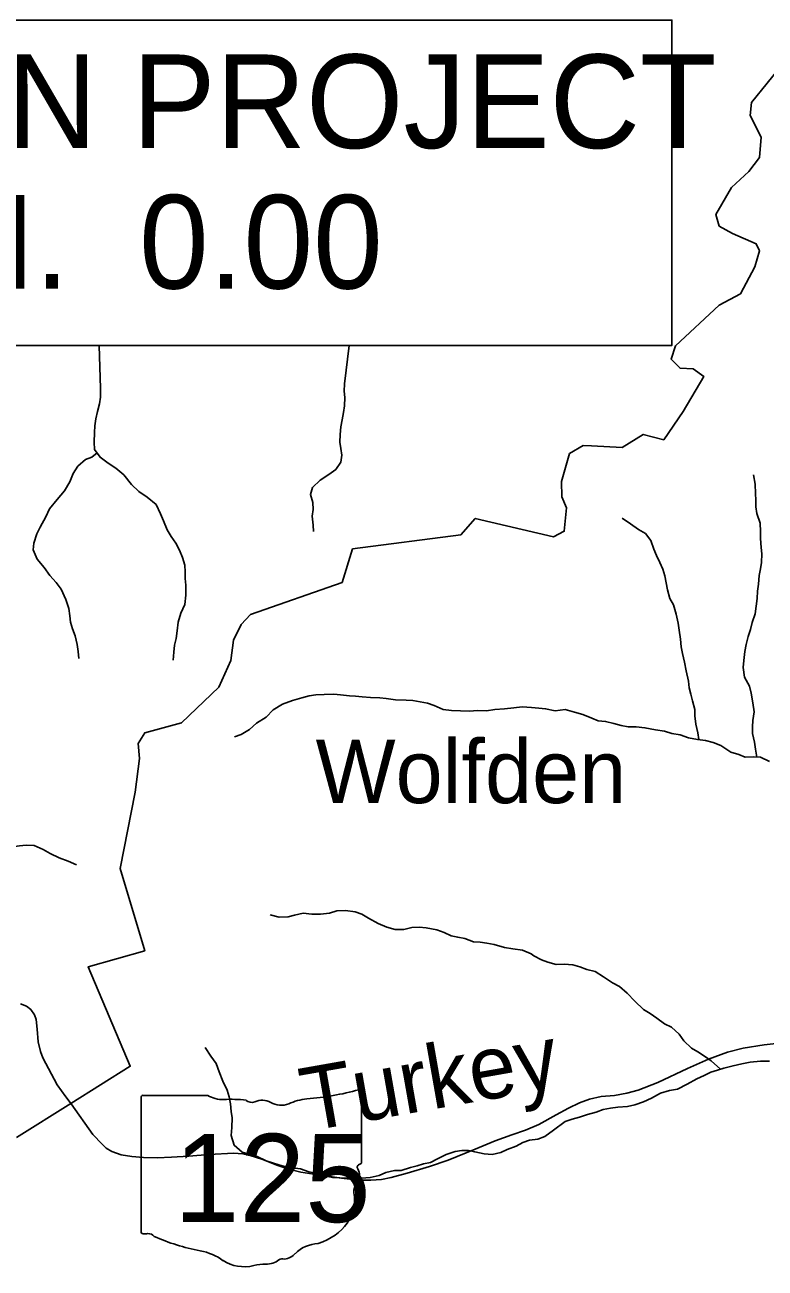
# Model space of a CAD drawing. Extents: x 0 to 34, y 0 to 22.
# Drawn here: x 3.475 to 4.582, y 17.294 to 19.152 of the extents above; entities that cross this region are included whole.
import ezdxf

# ---------------------------------------------------------------- set-up
doc = ezdxf.new("R2010")
doc.units = 0
for name, color, linetype in [('Default', 7, 'Continuous'), ('GM_X_Minor_River', 7, 'Continuous'), ('GM_X_Minor_River_Text', 7, 'Continuous'), ('GM_X_State_Location', 7, 'Continuous'), ('GM_X_State_Route', 7, 'Continuous'), ('GM_X_State_Shield', 7, 'Continuous'), ('SH_Text', 7, 'Continuous')]:
    doc.layers.add(name, color=color, linetype=linetype)

msp = doc.modelspace()

# ---------------------------------------------------------------- linework, layer by layer
at = {"layer": 'Default'}
for points in [[(4.632, 19.1229), (4.5616, 19.0361), (4.5599, 19.0167), (4.5761, 18.9842), (4.5739, 18.9539), (4.5577, 18.9328), (4.532, 18.9089), (4.5084, 18.8685), (4.5132, 18.8514), (4.5335, 18.8405), (4.5689, 18.8249), (4.5737, 18.8146), (4.5666, 18.7904), (4.5453, 18.75), (4.5136, 18.7333), (4.4481, 18.6723), (4.4414, 18.6522), (4.4549, 18.6388), (4.4746, 18.6381), (4.4907, 18.6265), (4.4594, 18.5742), (4.4305, 18.532), (4.3999, 18.54), (4.3683, 18.5203), (4.3226, 18.5229), (4.31, 18.5236), (4.2894, 18.5114), (4.2775, 18.4698), (4.278, 18.4466), (4.2854, 18.4302), (4.2819, 18.3953), (4.2655, 18.3871), (4.1488, 18.4144), (4.1273, 18.39), (3.9654, 18.3689), (3.9496, 18.3186), (3.8127, 18.271), (3.7985, 18.2556), (3.7872, 18.2322), (3.7831, 18.2022), (3.7652, 18.1622), (3.7096, 18.1086), (3.6545, 18.0938), (3.6445, 18.0779), (3.6465, 18.0555), (3.6402, 18.0051), (3.6176, 17.8911), (3.6545, 17.7681), (3.5702, 17.7442), (3.6328, 17.5954), (3.5442, 17.5398), (3.4629, 17.4891)], [(3.4629, 17.4891), (3.5442, 17.5398), (3.6328, 17.5954), (3.5702, 17.7442), (3.6545, 17.7681), (3.6176, 17.8911), (3.6402, 18.0051), (3.6465, 18.0555), (3.6445, 18.0779), (3.6545, 18.0938), (3.7096, 18.1086), (3.7652, 18.1622), (3.7831, 18.2022), (3.7872, 18.2322), (3.7985, 18.2556), (3.8127, 18.271), (3.9496, 18.3186), (3.9654, 18.3689), (4.1273, 18.39), (4.1488, 18.4144), (4.2655, 18.3871), (4.2819, 18.3953), (4.2854, 18.4302), (4.278, 18.4466), (4.2775, 18.4698), (4.2894, 18.5114), (4.31, 18.5236), (4.3226, 18.5229), (4.3683, 18.5203), (4.3999, 18.54), (4.4305, 18.532), (4.4594, 18.5742), (4.4907, 18.6265), (4.4746, 18.6381), (4.4549, 18.6388), (4.4414, 18.6522), (4.4481, 18.6723), (4.5136, 18.7333), (4.5453, 18.75), (4.5666, 18.7904), (4.5737, 18.8146), (4.5689, 18.8249), (4.5335, 18.8405), (4.5132, 18.8514), (4.5084, 18.8685), (4.532, 18.9089), (4.5577, 18.9328), (4.5739, 18.9539), (4.5761, 18.9842), (4.5599, 19.0167), (4.5616, 19.0361), (4.632, 19.1229)]]:
    msp.add_lwpolyline(points, dxfattribs=at)
at = {"layer": 'GM_X_Minor_River'}
for points in [[(3.5866, 18.673), (3.5885, 18.6087), (3.5884, 18.5958), (3.5868, 18.5859), (3.5841, 18.5742), (3.5814, 18.5632), (3.5802, 18.5526), (3.5797, 18.5427), (3.5792, 18.5283), (3.5796, 18.5176), (3.5878, 18.5058), (3.5999, 18.497), (3.6112, 18.4893), (3.6233, 18.4797), (3.6349, 18.4652), (3.6459, 18.4545), (3.658, 18.4461), (3.6715, 18.4354), (3.6783, 18.4213), (3.6827, 18.4106), (3.688, 18.3973), (3.694, 18.3874), (3.7011, 18.3774), (3.7067, 18.3671), (3.7112, 18.3561), (3.7145, 18.3443), (3.7148, 18.3344), (3.7148, 18.3246), (3.7162, 18.3147), (3.7161, 18.2999), (3.7145, 18.2858), (3.7087, 18.2726), (3.7045, 18.2593), (3.7033, 18.2464), (3.7017, 18.235), (3.6993, 18.2248), (3.6981, 18.2145), (3.6973, 18.2024)], [(3.9602, 18.673), (3.953, 18.6155), (3.9529, 18.6045), (3.9536, 18.595), (3.9531, 18.5828), (3.9519, 18.5726), (3.9499, 18.5616), (3.948, 18.5513), (3.9468, 18.54), (3.9463, 18.5282), (3.9478, 18.5187), (3.9492, 18.5088), (3.9476, 18.4986), (3.9404, 18.4876), (3.9297, 18.4801), (3.9167, 18.4718), (3.9053, 18.4605), (3.9022, 18.4502), (3.9059, 18.438), (3.9066, 18.4278), (3.905, 18.4179), (3.9064, 18.4042), (3.9071, 18.3947)], [(3.5833, 18.5123), (3.5757, 18.5059), (3.5662, 18.5025), (3.5544, 18.4923), (3.5478, 18.4814), (3.5424, 18.4689), (3.5348, 18.4556), (3.5237, 18.4428), (3.5122, 18.4288), (3.5068, 18.417), (3.498, 18.4015), (3.4934, 18.3913), (3.4888, 18.3773), (3.4879, 18.3674), (3.4939, 18.3537), (3.5041, 18.3411), (3.5127, 18.3293), (3.5221, 18.3186), (3.5296, 18.3086), (3.5364, 18.2934), (3.5412, 18.2797), (3.5426, 18.2687), (3.5437, 18.2592), (3.5467, 18.2493), (3.5508, 18.239), (3.5537, 18.2257), (3.5548, 18.2154), (3.5562, 18.2048)], [(4.5695, 18.0576), (4.5678, 18.0695), (4.5663, 18.0798), (4.5634, 18.0927), (4.5631, 18.1026), (4.5639, 18.1121), (4.5655, 18.1254), (4.5637, 18.1387), (4.5615, 18.1531), (4.5586, 18.1638), (4.5514, 18.1771), (4.5493, 18.1916), (4.5501, 18.2018), (4.5517, 18.2155), (4.554, 18.2257), (4.5568, 18.2379), (4.5603, 18.2485), (4.563, 18.2587), (4.5672, 18.2716), (4.5688, 18.2834), (4.5704, 18.2948), (4.5709, 18.3058), (4.5721, 18.316), (4.5733, 18.3289), (4.5753, 18.3392), (4.5769, 18.3487), (4.5773, 18.3612), (4.5762, 18.3707), (4.5752, 18.3844), (4.5753, 18.3946), (4.5746, 18.4072), (4.5698, 18.4216), (4.5683, 18.4315), (4.5684, 18.4418), (4.5677, 18.4517), (4.567, 18.4657), (4.5645, 18.4794)], [(4.4829, 18.0838), (4.4815, 18.094), (4.4785, 18.1066), (4.4771, 18.1191), (4.4768, 18.129), (4.4735, 18.1415), (4.4713, 18.1518), (4.4687, 18.1613), (4.4676, 18.1712), (4.4639, 18.1864), (4.4617, 18.1994), (4.4588, 18.2127), (4.4566, 18.2226), (4.4555, 18.234), (4.4537, 18.2473), (4.4523, 18.2579), (4.4493, 18.2712), (4.4452, 18.2853), (4.4396, 18.2948), (4.4363, 18.3078), (4.4322, 18.3287), (4.4293, 18.3386), (4.4248, 18.3485), (4.4196, 18.3588), (4.4158, 18.3683), (4.411, 18.3812), (4.4031, 18.3916), (4.3929, 18.3977), (4.3808, 18.4065), (4.3684, 18.4146)], [(4.5885, 18.0512), (4.5753, 18.0573), (4.5654, 18.0578), (4.5525, 18.0575), (4.5427, 18.0617), (4.531, 18.0652), (4.5159, 18.0748), (4.5045, 18.0794), (4.4932, 18.0822), (4.4811, 18.0841), (4.4674, 18.0865), (4.4553, 18.0911), (4.4428, 18.0931), (4.4315, 18.0962), (4.4182, 18.0986), (4.4023, 18.1014), (4.3894, 18.1026), (4.3773, 18.103), (4.3667, 18.1046), (4.3561, 18.1077), (4.3436, 18.1109), (4.3326, 18.1117), (4.3228, 18.1159), (4.3095, 18.1213), (4.297, 18.1248), (4.2834, 18.1287), (4.2682, 18.1269), (4.2538, 18.13), (4.244, 18.1309), (4.233, 18.1317), (4.219, 18.1325), (4.2064, 18.1311), (4.1924, 18.1297), (4.178, 18.1286), (4.1655, 18.1268), (4.1526, 18.1273), (4.1397, 18.1262), (4.1268, 18.1267), (4.1131, 18.1271), (4.1006, 18.1287), (4.0874, 18.1345), (4.0772, 18.1384), (4.0662, 18.1404), (4.0552, 18.1423), (4.0454, 18.1428), (4.0294, 18.1433), (4.0154, 18.1452), (4.006, 18.1464), (3.9919, 18.1465), (3.9798, 18.1477), (3.9699, 18.1486), (3.9605, 18.149), (3.9472, 18.1506), (3.9374, 18.1518), (3.9229, 18.1512), (3.9104, 18.1505), (3.9006, 18.149), (3.8895, 18.146), (3.8755, 18.142), (3.8607, 18.1367), (3.8466, 18.1285), (3.8359, 18.1175), (3.8218, 18.1081), (3.8111, 18.0987), (3.7985, 18.0912), (3.789, 18.0878)], [(3.443, 17.9225), (3.4539, 17.9232), (3.4675, 17.925), (3.4774, 17.9261), (3.4892, 17.9253), (3.5028, 17.9195), (3.513, 17.9133), (3.5266, 17.9072), (3.5402, 17.9018), (3.5527, 17.8967)], [(4.2324, 17.7633), (4.2192, 17.769), (4.2048, 17.771), (4.1923, 17.773), (4.1768, 17.7773), (4.1658, 17.7796), (4.1563, 17.7808), (4.1461, 17.7817), (4.1332, 17.7863), (4.1226, 17.7883), (4.1128, 17.7902), (4.1022, 17.7956), (4.0912, 17.7995), (4.0753, 17.8022), (4.0651, 17.8034), (4.0537, 17.8028), (4.0419, 17.7998), (4.0291, 17.7999), (4.0166, 17.8034), (4.0037, 17.8088), (3.9893, 17.8168), (3.9791, 17.8226), (3.9693, 17.8265), (3.9549, 17.8281), (3.9416, 17.8278), (3.9306, 17.8244), (3.9173, 17.823), (3.9044, 17.8227), (3.8916, 17.8243), (3.8787, 17.8213), (3.8688, 17.8188), (3.8555, 17.8181), (3.8423, 17.8216)], [(4.5152, 17.5912), (4.5017, 17.6036), (4.4915, 17.6105), (4.4816, 17.617), (4.4722, 17.6223), (4.4604, 17.6334), (4.4537, 17.6433), (4.4419, 17.6537), (4.4317, 17.659), (4.42, 17.6675), (4.4101, 17.6743), (4.4003, 17.6805), (4.3871, 17.6927), (4.3761, 17.7045), (4.3644, 17.7145), (4.3538, 17.7202), (4.3405, 17.729), (4.328, 17.7371), (4.3155, 17.7402), (4.3049, 17.7441), (4.2946, 17.7471), (4.2817, 17.748), (4.2699, 17.7477), (4.2574, 17.7512), (4.2476, 17.7546), (4.2363, 17.7607), (4.2324, 17.7633)], [(3.7536, 17.6105), (3.745, 17.6234)], [(4.5887, 17.6031), (4.5751, 17.6032), (4.5598, 17.6017), (4.5473, 17.5991), (4.5343, 17.5962), (4.5202, 17.5928), (4.5107, 17.5898), (4.5008, 17.5865), (4.4909, 17.5816), (4.4799, 17.5767), (4.4654, 17.5685), (4.4512, 17.5613), (4.4394, 17.5591), (4.4257, 17.5554), (4.4124, 17.5479), (4.4002, 17.5422), (4.3872, 17.5378), (4.3762, 17.5355), (4.3617, 17.5345), (4.3507, 17.5327), (4.3401, 17.5308), (4.3294, 17.5271), (4.3168, 17.5234), (4.3046, 17.5192), (4.2936, 17.5163), (4.2833, 17.5129), (4.2657, 17.5001), (4.2528, 17.4907), (4.2421, 17.4866), (4.2299, 17.4851), (4.22, 17.4814), (4.2097, 17.4761), (4.1964, 17.4709), (4.1868, 17.4668), (4.1739, 17.4638), (4.1621, 17.4646), (4.1481, 17.4674), (4.1386, 17.4697), (4.1287, 17.4694), (4.1188, 17.4679), (4.1051, 17.4634), (4.0925, 17.457), (4.0818, 17.4518), (4.0716, 17.4496), (4.062, 17.4466), (4.0518, 17.444), (4.038, 17.4399), (4.0282, 17.4395), (4.0152, 17.4366), (4.0049, 17.4321), (3.9916, 17.4291), (3.9787, 17.4284), (3.9665, 17.4278), (3.957, 17.4282), (3.9464, 17.4286), (3.9353, 17.4294), (3.9205, 17.4326), (3.9095, 17.4357), (3.9, 17.4376), (3.8875, 17.4419), (3.8754, 17.4438), (3.8598, 17.4466), (3.8469, 17.4505), (3.8359, 17.4543), (3.8226, 17.4605), (3.8101, 17.464), (3.8003, 17.467), (3.7882, 17.4774), (3.7837, 17.4922), (3.7849, 17.504), (3.7854, 17.5184), (3.7839, 17.5279), (3.7828, 17.5393), (3.781, 17.5496), (3.778, 17.5598), (3.7713, 17.5732), (3.766, 17.5872), (3.7612, 17.5998), (3.7536, 17.6105)]]:
    msp.add_lwpolyline(points, dxfattribs=at)
at = {"layer": 'GM_X_State_Route'}
msp.add_lwpolyline([(3.469, 17.689), (3.478, 17.6851), (3.4841, 17.6802), (3.4897, 17.6725), (3.492, 17.6652), (3.4939, 17.6507), (3.4953, 17.632), (3.4986, 17.6175), (3.5023, 17.608), (3.5238, 17.5679), (3.5367, 17.5498), (3.5445, 17.5393), (3.5771, 17.4936), (3.5911, 17.4789), (3.597, 17.4729), (3.6054, 17.4681), (3.6195, 17.4629), (3.6354, 17.4607), (3.6527, 17.459), (3.6732, 17.4587), (3.6944, 17.4598), (3.7204, 17.4612), (3.751, 17.4637), (3.7874, 17.4657), (3.8011, 17.4645), (3.8078, 17.4633), (3.8122, 17.4622), (3.8294, 17.4564), (3.8523, 17.4477), (3.8684, 17.4422), (3.8881, 17.4372), (3.9075, 17.4344), (3.9488, 17.4282), (3.965, 17.4262), (3.9803, 17.4254), (3.9927, 17.4252), (4.0088, 17.4264), (4.0231, 17.4291), (4.0469, 17.4356), (4.0802, 17.4458), (4.1081, 17.4549), (4.1487, 17.4715), (4.1785, 17.4841), (4.2034, 17.493), (4.224, 17.4999), (4.2439, 17.5084), (4.2699, 17.5231), (4.2883, 17.5328), (4.3044, 17.5408), (4.3197, 17.5463), (4.3369, 17.5501), (4.357, 17.5519), (4.3753, 17.5551), (4.3925, 17.5596), (4.4216, 17.5714), (4.4659, 17.5921), (4.4975, 17.6063), (4.5261, 17.6166), (4.5495, 17.6224), (4.5809, 17.6275), (4.6029, 17.6301)], dxfattribs=at)
at = {"layer": 'GM_X_State_Shield'}
for p, q in [((3.6491, 17.5486), (3.6491, 17.3484)), ((3.7489, 17.552), (3.6524, 17.552)), ((3.9787, 17.4523), (3.9787, 17.557)), ((3.9787, 17.4523), (3.9787, 17.4523))]:
    msp.add_line(p, q, dxfattribs=at)
for centre, major_axis, start_param, end_param in [((3.6529, 17.549), (0.00382, 0), 1.712693, 3.28349), ((3.7719, 17.5752), (0.037, 0), 4.042523, 4.731795), ((3.7842, 17.4397), (0.133, 0), 1.404758, 1.657858), ((3.8143, 17.55), (0.0107, 0), 3.836095, 5.185415), ((3.83, 17.5269), (0.0222, 0), 0.950623, 2.079405), ((3.9059, 17.4909), (0.0703, 0), 1.699011, 2.107814), ((3.8613, 17.8248), (0.3495, 0), 4.814394, 5.042369), ((3.9751, 17.5574), (0.00367, 0), 6.141152, 7.989035), ((3.8587, 17.5586), (0.0267, 0), 4.081561, 5.145723), ((3.9748, 17.4519), (0.00393, 0), 5.05454, 6.418171), ((3.9779, 17.4446), (0.00568, 0), 1.883978, 3.671073), ((3.9417, 17.4314), (0.0341, 0), 5.934695, 6.695948), ((3.9919, 17.4085), (0.0248, 0), 2.387724, 3.262537), ((3.8809, 17.3952), (0.0874, 0), 5.101752, 6.440018), ((3.6529, 17.348), (0.00385, 0), 3.00124, 4.508301), ((3.6535, 17.3685), (0.0294, 0), 4.665946, 4.897461), ((3.6595, 17.3369), (0.0106, 0), 0.519207, 1.627899), ((3.7934, 17.5167), (0.2524, 0), 4.195997, 4.488961), ((3.9178, 17.2923), (0.0479, 0), 1.647645, 2.488434), ((3.7181, 17.2585), (0.079, 0), 0.823519, 1.323587), ((3.8035, 17.3359), (0.0501, 0), 4.026481, 4.996735), ((3.8361, 17.3209), (0.0267, 0), 4.691044, 5.507374), ((3.8603, 17.3015), (0.00752, 0), 1.147584, 2.315152), ((3.8571, 17.329), (0.0282, 0), 4.937069, 5.64225), ((3.8325, 17.2667), (0.0412, 0), 1.495662, 1.94098)]:
    msp.add_ellipse(centre, major_axis=major_axis, ratio=0.8, start_param=start_param, end_param=end_param, dxfattribs=at)
at = {"layer": 'SH_Text'}
msp.add_lwpolyline([(2.9469, 19.1594), (4.4427, 19.1594), (4.4427, 18.673), (2.9469, 18.673)], close=True, dxfattribs=at)

# ---------------------------------------------------------------- texts
at = {"layer": 'GM_X_Minor_River_Text'}
for s, rotation, p in [('Wolfden', 0.0002, (3.9101, 17.9888)), ('Turkey', 10.001, (3.8971, 17.4978))]:
    msp.add_text(s, height=0.09469, rotation=rotation, dxfattribs=at).set_placement(p)
at = {"layer": 'GM_X_State_Location'}
for s in ['s', 'r']:
    msp.add_text(s, height=0.000189, dxfattribs=at).set_placement((3.8102, 17.4352))
msp.add_text('125', height=0.000189, rotation=0, dxfattribs=at).set_placement((3.7434, 17.4214))
at = {"layer": 'GM_X_State_Shield'}
msp.add_text('125', height=0.13184, dxfattribs=at).set_placement((3.6983, 17.3626))
at = {"layer": 'SH_Text'}
for s, p in [('BEGIN PROJECT', (3.0011, 18.9679)), ('S.L.M.  0.00', (3.0011, 18.7579))]:
    msp.add_text(s, height=0.14, dxfattribs=at).set_placement(p)

doc.saveas('drawing.dxf')
